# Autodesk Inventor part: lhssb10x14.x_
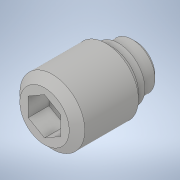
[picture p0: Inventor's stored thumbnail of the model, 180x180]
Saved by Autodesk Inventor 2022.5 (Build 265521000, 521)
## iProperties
Created: 2021-02
Part Number: lhssb10x14.x_
Material: 一般
Document SubType Name: Modeling
Designer: ImaoCorp
Density: 1 g/cm^3
Appearance: 既定
Sending System: SOLIDWORKS 2019-2019304
MC: AMD64
MC_MODEL: Intel64 Family 6 Model 60 Stepping 3, GenuineIntel
OS: Windows_NT
FRU: Parasolid Version 31.0, build 290,  9- 1-2019
FORMAT: text
GUISE: transmit
KEY: lhssb10x14
FILE: lhssb10x14.x_t
DATE: Mon Feb 22 14:55:56 2021
Author: ImaoCorp
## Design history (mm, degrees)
feature "Base1"
node "ソリッド1"
